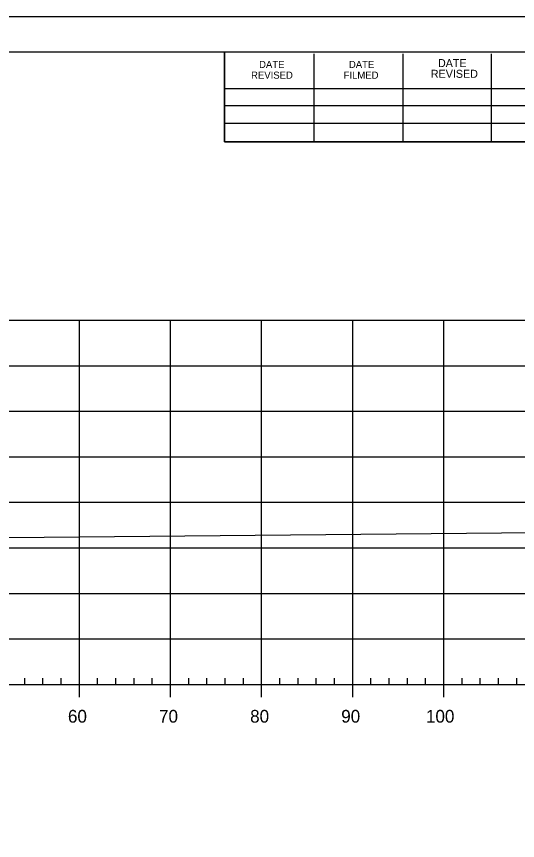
# Model space of a CAD drawing. Extents: x 1370843 to 1371177, y 380307 to 382654.
# Drawn here: x 1371066.8 to 1371121.8, y 381923.7 to 382014.2 of the extents above; entities that cross this region are included whole.
import ezdxf

# ---------------------------------------------------------------- set-up
doc = ezdxf.new("R2010")
doc.units = 0
for name, color, linetype in [('R_Axis', 7, 'Continuous'), ('R_Axis Annot', 7, 'Continuous'), ('R_Border', 7, 'Continuous'), ('R_Exist Surface', 7, 'Continuous'), ('R_Grid', 7, 'Continuous'), ('R_No Plot', 7, 'Continuous')]:
    doc.layers.add(name, color=color, linetype=linetype)

msp = doc.modelspace()

# ---------------------------------------------------------------- linework, layer by layer
at = {"layer": 'R_Axis'}
for p, q in [((1370868.709, 381940.814), (1371158.709, 381940.814)), ((1371067.709, 381940.814), (1371067.709, 381941.514)), ((1371069.709, 381940.814), (1371069.709, 381941.514)), ((1371071.709, 381940.814), (1371071.709, 381941.514)), ((1371073.709, 381939.414), (1371073.709, 381940.814)), ((1371075.709, 381940.814), (1371075.709, 381941.514)), ((1371077.709, 381940.814), (1371077.709, 381941.514)), ((1371079.709, 381940.814), (1371079.709, 381941.514)), ((1371081.709, 381940.814), (1371081.709, 381941.514)), ((1371083.709, 381939.414), (1371083.709, 381940.814)), ((1371085.709, 381940.814), (1371085.709, 381941.514)), ((1371087.709, 381940.814), (1371087.709, 381941.514)), ((1371089.709, 381940.814), (1371089.709, 381941.514)), ((1371091.709, 381940.814), (1371091.709, 381941.514)), ((1371093.709, 381939.414), (1371093.709, 381940.814)), ((1371095.709, 381940.814), (1371095.709, 381941.514)), ((1371097.709, 381940.814), (1371097.709, 381941.514)), ((1371099.709, 381940.814), (1371099.709, 381941.514)), ((1371101.709, 381940.814), (1371101.709, 381941.514)), ((1371103.709, 381939.414), (1371103.709, 381940.814)), ((1371105.709, 381940.814), (1371105.709, 381941.514)), ((1371107.709, 381940.814), (1371107.709, 381941.514)), ((1371109.709, 381940.814), (1371109.709, 381941.514)), ((1371111.709, 381940.814), (1371111.709, 381941.514)), ((1371113.709, 381939.414), (1371113.709, 381940.814)), ((1371115.709, 381940.814), (1371115.709, 381941.514)), ((1371117.709, 381940.814), (1371117.709, 381941.514)), ((1371119.709, 381940.814), (1371119.709, 381941.514)), ((1371121.709, 381940.814), (1371121.709, 381941.514))]:
    msp.add_line(p, q, dxfattribs=at)
at = {"layer": 'R_Border'}
for p, q in [((1370855.709, 382010.274), (1371171.889, 382010.274)), ((1371089.629, 382000.394), (1371089.629, 382010.274)), ((1371099.489, 382000.394), (1371099.489, 382010.074)), ((1371109.249, 382000.394), (1371109.249, 382010.074)), ((1371118.929, 382000.394), (1371118.929, 382010.074)), ((1371089.629, 382006.254), (1371128.789, 382006.254)), ((1371089.629, 382004.394), (1371128.789, 382004.394)), ((1371089.629, 382000.394), (1371089.629, 382002.454)), ((1371089.629, 382002.454), (1371128.789, 382002.454)), ((1371171.889, 382000.394), (1371089.629, 382000.394))]:
    msp.add_line(p, q, dxfattribs=at)
at = {"layer": 'R_Exist Surface'}
msp.add_line((1371069.832, 381956.991), (1371158.709, 381957.81), dxfattribs=at)
msp.add_lwpolyline([(1370893.638, 381956.7), (1370894.957, 381956.635), (1370896.693, 381956.549), (1370899.082, 381956.431), (1370903.698, 381956.136), (1370914.261, 381955.669), (1370937.349, 381956.286), (1370947.817, 381957.436), (1370956.834, 381959.948), (1370968.622, 381963.14), (1370975.459, 381964.107), (1370975.762, 381964.148), (1370979.053, 381964.22), (1370986.461, 381964.38), (1370987.417, 381964.358), (1370995.771, 381964.151), (1370997.649, 381963.873), (1371003.518, 381962.984), (1371015.981, 381960.195), (1371022.824, 381958.659), (1371045.998, 381957.731), (1371064.486, 381956.941), (1371069.832, 381956.991)], dxfattribs=at)
at = {"layer": 'R_Grid'}
for p, q in [((1370868.709, 381980.814), (1371158.709, 381980.814)), ((1371073.709, 381940.814), (1371073.709, 381980.814)), ((1371083.709, 381940.814), (1371083.709, 381980.814)), ((1371093.709, 381940.814), (1371093.709, 381980.814)), ((1371103.709, 381940.814), (1371103.709, 381980.814)), ((1371113.709, 381940.814), (1371113.709, 381980.814)), ((1370868.709, 381975.814), (1371158.709, 381975.814)), ((1370868.709, 381970.814), (1371158.709, 381970.814)), ((1370868.709, 381965.814), (1371158.709, 381965.814)), ((1370868.709, 381960.814), (1371158.709, 381960.814)), ((1370868.709, 381955.814), (1371158.709, 381955.814)), ((1370868.709, 381950.814), (1371158.709, 381950.814)), ((1370868.709, 381945.814), (1371158.709, 381945.814)), ((1370868.709, 381940.814), (1371158.709, 381940.814))]:
    msp.add_line(p, q, dxfattribs=at)
at = {"layer": 'R_No Plot'}
msp.add_line((1370843.308, 382014.169), (1371176.642, 382014.169), dxfattribs=at)
for points in [[(1370843.302, 382014.169), (1371176.642, 382014.169), (1371176.642, 381800.831), (1370843.302, 381800.831)], [(1371089.629, 382010.274), (1371089.629, 382000.394), (1371125.361, 382000.394), (1371125.361, 381997.474), (1371148.561, 381997.474), (1371148.561, 381973.142), (1371171.889, 381973.142), (1371171.889, 381804.814), (1370855.709, 381804.814), (1370855.709, 382010.274)]]:
    msp.add_lwpolyline(points, close=True, dxfattribs=at)

# ---------------------------------------------------------------- texts
at = {"layer": 'R_Axis Annot'}
for s, p in [('60', (1371072.448, 381936.614)), ('70', (1371082.448, 381936.614)), ('80', (1371092.448, 381936.614)), ('90', (1371102.448, 381936.614)), ('100', (1371111.748, 381936.614))]:
    msp.add_text(s, height=1.4, dxfattribs=at).set_placement(p)
at = {"layer": 'R_Border'}
for s, height, p in [('DATE', 0.7819, (1371093.429, 382008.514)), ('DATE', 0.7819, (1371103.289, 382008.514)), ('DATE', 0.8792, (1371113.069, 382008.614)), ('REVISED', 0.7819, (1371092.549, 382007.334)), ('FILMED', 0.7819, (1371102.709, 382007.334)), ('REVISED', 0.8792, (1371112.289, 382007.434))]:
    msp.add_text(s, height=height, rotation=360, dxfattribs=at).set_placement(p)

doc.saveas('drawing.dxf')
